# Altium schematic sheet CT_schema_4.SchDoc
size 283 x 147 mm
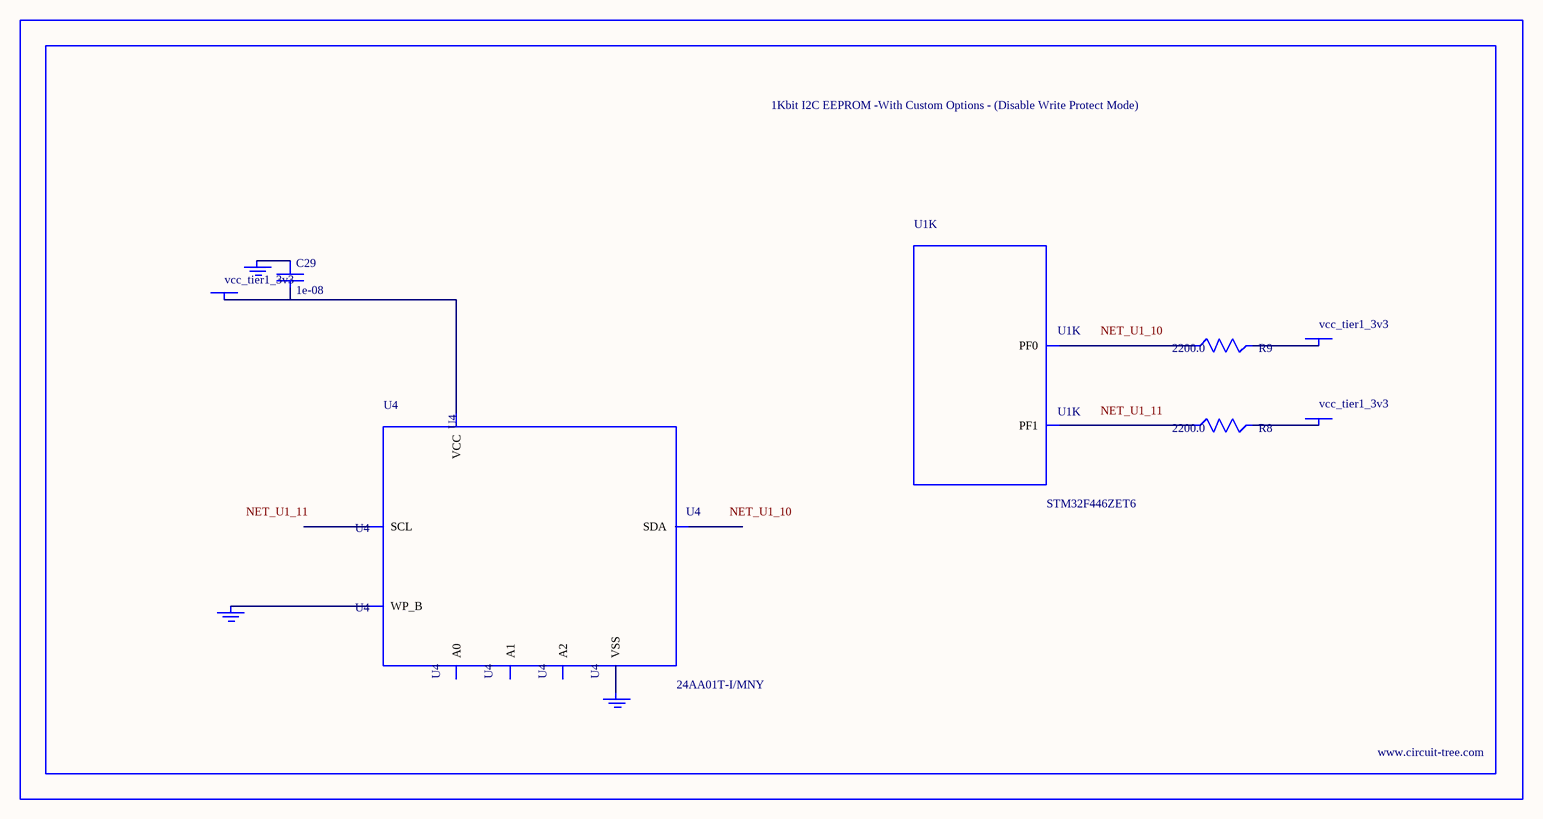
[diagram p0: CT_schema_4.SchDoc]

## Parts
BORDER3  (no value)
C29  1e-08  [C0402]
GND_INSTANCE_3_0  (no value)
GND_INSTANCE_3_1  (no value)
GND_INSTANCE_3_2  (no value)
POWER_INSTANCE_3_0  vcc_tier1_3v3
POWER_INSTANCE_3_1  vcc_tier1_3v3
POWER_INSTANCE_3_2  vcc_tier1_3v3
R8  2200.0  [R0603]
R9  2200.0  [R0603]
U1  STM32F446ZET6  [LQFP144]  (part K of 11)
U4  24AA01T-I/MNY  [TDFN-8/6MM]

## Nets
NetC29_1: C29.1 GND_INSTANCE_3_1.0(GND)
NetC29_2: C29.2 POWER_INSTANCE_3_0.0(PWR) U4.8(VCC)
NetGND_INSTANCE_3_0_0: GND_INSTANCE_3_0.0(GND) U4.7(WP_B)
NetGND_INSTANCE_3_2_0: GND_INSTANCE_3_2.0(GND) U4.4(VSS)
NetPOWER_INSTANCE_3_1_0: POWER_INSTANCE_3_1.0(PWR) R9.2
NetPOWER_INSTANCE_3_2_0: POWER_INSTANCE_3_2.0(PWR) R8.2
NetR8_1: R8.1 U1.11(PF1)
NetR9_1: R9.1 U1.10(PF0)

Not connected (* = marked no-connect by the designer): U4 1(A0) 2(A1) 3(A2) 5(SDA) 6(SCL)

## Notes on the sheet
- Labels drawn without touching a wire or pin: NET_U1_10, NET_U1_11

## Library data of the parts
BORDER3 = BORDER_PAGE3
C29 = C0402C103K3RAC
GND_INSTANCE_3_0-GND_INSTANCE_3_2 = GND
POWER_INSTANCE_3_0-POWER_INSTANCE_3_2 = PWR
R8 R9 = RC0603JR-072K2L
